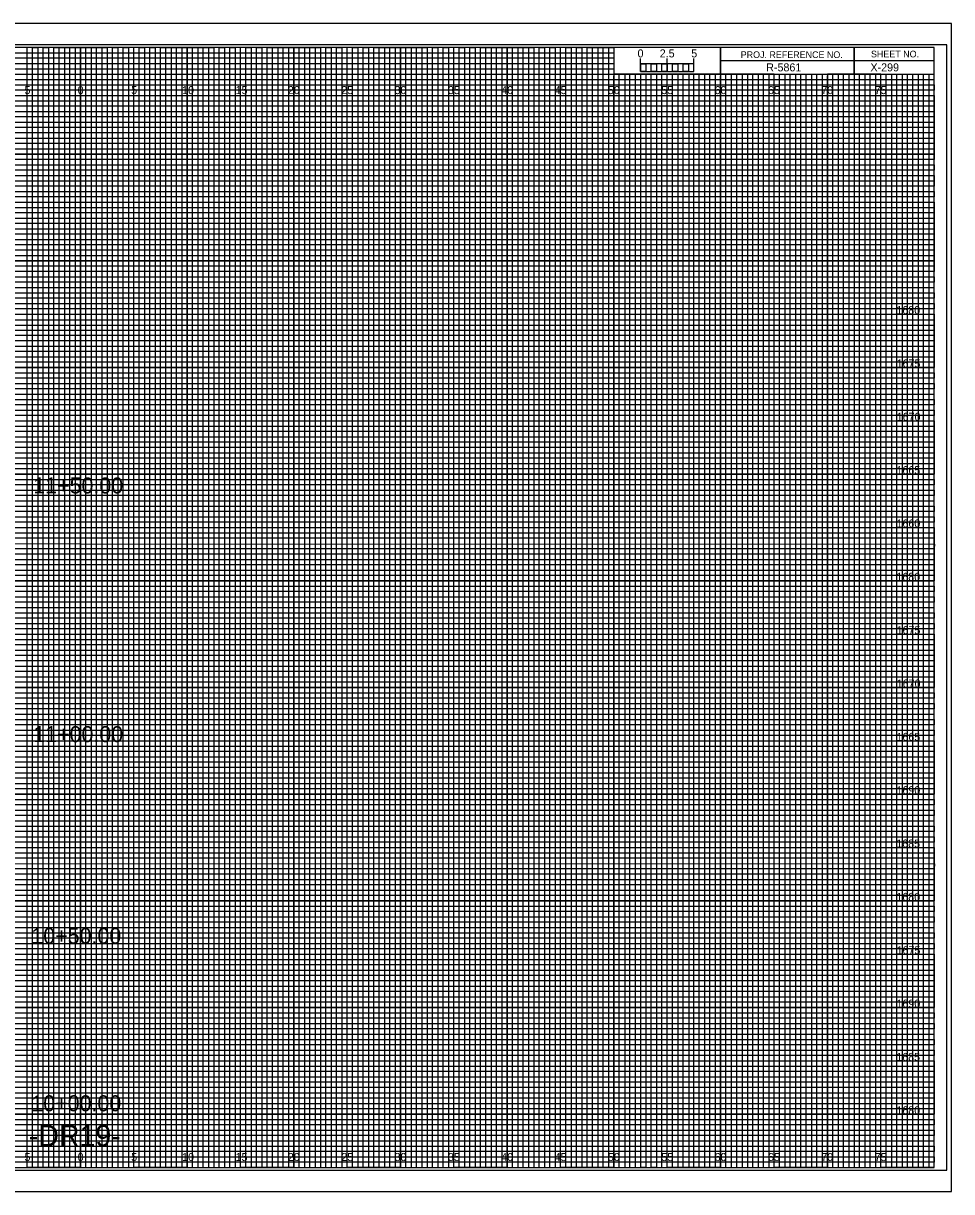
# Model space of a CAD drawing. Extents: x -7 to 162, y -2 to 107.
# Drawn here: x 74.6 to 161.7, y -2.3 to 107.3 of the extents above; entities that cross this region are included whole.
import ezdxf

# ---------------------------------------------------------------- set-up
doc = ezdxf.new("R2010")
doc.units = 0
for name, color, linetype in [('Prop XS Alignment Label', 7, 'Continuous'), ('Prop XS Bar Scale Labels', 7, 'Continuous'), ('Prop XS Elevation Labels', 7, 'Continuous'), ('Prop XS Offset Labels', 7, 'Continuous'), ('Prop XS Project Number', 7, 'Continuous'), ('Prop XS Sheet Number', 7, 'Continuous'), ('Prop XS Station Labels', 7, 'Continuous'), ('Sheet Cross Section CELL', 7, 'Continuous'), ('Sheet Cross Section Grid Major CELL', 7, 'Continuous'), ('Sheet Cross Section Grid Middle CELL', 7, 'Continuous'), ('Sheet Cross Section Grid Minor 1 CELL', 7, 'Continuous'), ('Sheet Cross Section Grid Minor 2 CELL', 7, 'Continuous'), ('Sheet Cross Section Scale CELL', 7, 'Continuous'), ('Sheet Cutting Line CELL', 7, 'Continuous'), ('Sheet DOT Grid CELL', 7, 'Continuous'), ('Sheet Plot Border Inside CELL', 7, 'Continuous'), ('Sheet Plot Border Outside CELL', 7, 'Continuous')]:
    doc.layers.add(name, color=color, linetype=linetype)

msp = doc.modelspace()

# ---------------------------------------------------------------- linework, layer by layer
at = {"layer": 'Sheet Cross Section CELL'}
for p, q in [((152.5, 105), (152.5, 102.5)), ((152.5, 102.5), (152.5, 105)), ((160, 103.75), (140, 103.75)), ((140, 103.75), (140, 102.5)), ((140, 102.5), (160, 102.5))]:
    msp.add_line(p, q, dxfattribs=at)
for points in [[(160, 105), (0, 105), (0, 0), (160, 0)], [(140, 105), (130, 105), (130, 102.52), (140, 102.52)], [(160, 105), (140, 105), (140, 102.5), (160, 102.5)]]:
    msp.add_lwpolyline(points, close=True, dxfattribs=at)
at = {"layer": 'Sheet Cross Section Grid Major CELL'}
for p, q in [((75, 105), (70, 105)), ((75, 0), (75, 105)), ((85, 105), (80, 105)), ((80, 105), (80, 0)), ((85, 0), (85, 105)), ((95, 105), (90, 105)), ((90, 105), (90, 0)), ((95, 0), (95, 105)), ((105, 105), (100, 105)), ((100, 105), (100, 0)), ((105, 0), (105, 105)), ((115, 105), (110, 105)), ((110, 105), (110, 0)), ((115, 0), (115, 105)), ((125, 105), (120, 105)), ((120, 105), (120, 0)), ((125, 0), (125, 105)), ((130, 105), (130, 0)), ((135, 0), (135, 102.5)), ((145, 102.5), (140, 102.5)), ((140, 102.5), (140, 0)), ((145, 0), (145, 102.5)), ((155, 102.5), (150, 102.5)), ((150, 102.5), (150, 0)), ((155, 0), (155, 102.5)), ((80, 0), (75, 0)), ((90, 0), (85, 0)), ((100, 0), (95, 0)), ((110, 0), (105, 0)), ((120, 0), (115, 0)), ((130, 0), (125, 0)), ((140, 0), (135, 0)), ((150, 0), (145, 0)), ((160, 0), (155, 0)), ((160, 0), (160, 0))]:
    msp.add_line(p, q, dxfattribs=at)
for points in [[(0, 100), (160, 100), (160, 95), (0, 95)], [(0, 90), (160, 90), (160, 85), (0, 85)], [(0, 80), (160, 80), (160, 75), (0, 75)], [(0, 70), (160, 70), (160, 65), (0, 65)], [(0, 60), (160, 60), (160, 55), (0, 55)], [(0, 50), (160, 50), (160, 45), (0, 45)], [(0, 40), (160, 40), (160, 35), (0, 35)], [(0, 30), (160, 30), (160, 25), (0, 25)], [(0, 20), (160, 20), (160, 15), (0, 15)], [(0, 10), (160, 10), (160, 5), (0, 5)]]:
    msp.add_lwpolyline(points, dxfattribs=at)
at = {"layer": 'Sheet Cross Section Grid Middle CELL'}
for points in [[(72.5, 0), (77.5, 0), (77.5, 105), (82.5, 105), (82.5, 0), (87.5, 0), (87.5, 105), (92.5, 105), (92.5, 0), (97.5, 0), (97.5, 105), (102.5, 105), (102.5, 0), (107.5, 0), (107.5, 105), (112.5, 105), (112.5, 0), (117.5, 0), (117.5, 105), (122.5, 105), (122.5, 0), (127.5, 0), (127.5, 105), (129.97, 105), (130, 105), (130, 102.5), (132.5, 102.5), (132.5, 0), (137.5, 0), (137.5, 102.5), (142.5, 102.5), (142.5, 0), (147.5, 0), (147.5, 102.5), (152.5, 102.5), (152.5, 0), (157.5, 0), (157.5, 102.5)], [(0, 102.5), (137.5, 102.5)], [(0, 92.5), (160, 92.5), (160, 97.5), (0, 97.5)], [(0, 82.5), (160, 82.5), (160, 87.5), (0, 87.5)], [(0, 72.5), (160, 72.5), (160, 77.5), (0, 77.5)], [(0, 62.5), (160, 62.5), (160, 67.5), (0, 67.5)], [(0, 52.5), (160, 52.5), (160, 57.5), (0, 57.5)], [(0, 42.5), (160, 42.5), (160, 47.5), (0, 47.5)], [(0, 32.5), (160, 32.5), (160, 37.5), (0, 37.5)], [(0, 22.5), (160, 22.5), (160, 27.5), (0, 27.5)], [(0, 12.5), (160, 12.5), (160, 17.5), (0, 17.5)], [(0, 2.5), (160, 2.5), (160, 7.5), (0, 7.5)]]:
    msp.add_lwpolyline(points, dxfattribs=at)
at = {"layer": 'Sheet Cross Section Grid Minor 1 CELL'}
for p, q in [((0, 104.5), (130, 104.5)), ((130, 104.5), (130, 103.99)), ((130, 103.99), (0, 103.99)), ((0, 103.5), (130, 103.5)), ((130, 102.95), (0, 102.95)), ((130, 103.5), (130, 102.95)), ((0, 102), (160, 102))]:
    msp.add_line(p, q, dxfattribs=at)
for points in [[(0, 101.5), (135, 101.5), (160, 101.5), (160, 101), (0, 101)], [(0, 100.5), (160, 100.5), (160, 99.5), (0, 99.5)], [(0, 99), (160, 99), (160, 98.5), (0, 98.49)], [(0, 98), (160, 98), (160, 97), (0, 97)], [(0, 96.5), (160, 96.5), (160, 96), (0, 96)], [(0, 95.5), (160, 95.5), (160, 94.5), (0, 94.5)], [(0, 94), (160, 94), (160, 93.5), (0, 93.5)], [(0, 93), (160, 93), (160, 92), (0, 92)], [(0, 91.5), (160, 91.5), (160, 91), (0, 91)], [(0, 90.5), (160, 90.5), (160, 89.5), (0, 89.5)], [(0, 89), (160, 89), (160, 88.5), (0, 88.5)], [(0, 88), (160, 88), (160, 86.98), (160, 86.5), (160, 86), (0, 86)], [(0, 87), (160, 87), (160, 86.5), (0, 86.5)], [(0, 85.5), (160, 85.5), (160, 84.5), (0, 84.52)], [(0, 84.52), (160, 84.5), (160, 84), (0, 84)], [(0, 83.5), (160, 83.5), (160, 83), (0, 83)], [(0, 82), (160, 82), (160, 81.5), (0, 81.5)], [(0, 81), (160, 81), (160, 80.5), (0, 80.5)], [(-0.04, 79.45), (160, 79.45), (160, 78.94), (-0.04, 78.94)], [(0, 78.5), (160, 78.5), (160, 78), (0, 78)], [(0, 77), (160, 77), (160, 76.5), (0, 76.5)], [(0, 76), (160, 76), (160, 75.5), (0, 75.5)], [(0, 74.5), (160, 74.5), (160, 74), (0, 74)], [(0, 73.5), (160, 73.5), (160, 73), (0, 73)], [(0, 72), (160, 72), (160, 71.5), (0, 71.5)], [(0, 71), (160, 71), (160, 70.5), (0, 70.5)], [(0, 69.5), (160, 69.5), (160, 68.99), (0, 69)], [(0, 68.5), (160, 68.5), (160, 68), (0, 68)], [(0, 67), (160, 67), (160, 66.5), (0, 66.5)], [(0, 66), (160, 66), (160, 65.5), (0, 65.5)], [(0, 64.5), (160, 64.5), (160, 64), (0, 64)], [(0, 63.5), (160, 63.5), (160, 63), (0, 63)], [(0, 62), (160, 62), (160, 61.5), (0, 61.5)], [(0, 61), (160, 61), (160, 60.5), (0, 60.5)], [(0, 59.5), (160, 59.5), (160, 59), (0, 59)], [(0, 58.5), (160.03, 58.45), (160, 58), (0, 58)], [(0, 57), (160, 57), (160, 56.5), (0, 56.5)], [(0, 56), (160, 56), (160, 55.5), (0, 55.5)], [(0, 54.5), (160, 54.5), (160, 54), (0, 54)], [(0, 53.5), (160, 53.5), (160, 53), (0, 53)], [(0, 52), (160, 52), (160, 51.5), (0, 51.5)], [(0, 51), (160, 51), (160, 50.5), (0, 50.5)], [(0, 49.5), (160, 49.5), (160, 49), (0, 49)], [(0, 48.5), (160, 48.5), (160, 48), (0, 48)], [(0, 47), (160, 47), (160, 46.5), (0, 46.5)], [(0, 46), (160, 46), (160, 45.5), (0, 45.5)], [(0, 44.5), (160, 44.5), (160, 44), (0, 44)], [(0, 43.5), (160, 43.5), (160, 43), (0, 43)], [(0, 42), (160, 42), (160, 41.5), (0, 41.5)], [(0, 41), (160, 41), (160, 40.5), (0, 40.5)], [(0, 39.5), (160, 39.5), (160, 38.99), (0, 39)], [(0, 38.5), (160, 38.5), (160, 38), (0, 38)], [(0, 37), (160, 37), (160, 36.5), (0, 36.5)], [(0, 36), (160, 36), (160, 35.5), (0, 35.5)], [(0, 34.5), (160, 34.5), (160, 34), (0, 34)], [(0, 33.5), (160, 33.5), (160, 33), (0, 33)], [(0, 32), (160, 32), (160, 31.5), (0, 31.5)], [(0, 31), (160, 31), (160, 30.5), (0, 30.5)], [(0, 29.5), (160, 29.5), (160, 29), (0, 29)], [(0, 28.5), (160.03, 28.46), (160, 28), (0, 28)], [(0, 27), (160, 27), (160, 26.5), (0, 26.5)], [(0, 26), (160, 26), (160, 25.5), (0, 25.5)], [(0, 24.5), (160, 24.5), (160, 24), (0, 24)], [(0, 23.5), (160, 23.5), (160, 23), (0, 23)], [(0, 22), (160, 22), (160, 21.5), (0, 21.5)], [(0, 21), (160, 21), (160, 20.5), (0, 20.5)], [(0, 19.5), (160, 19.5), (160, 19), (0, 19)], [(0, 18.5), (160, 18.5), (160, 18), (0, 18)], [(0, 17), (160, 17), (160, 16.5), (0, 16.5)], [(0, 16), (160, 16), (160, 15.5), (0, 15.5)], [(0, 14.5), (160, 14.5), (160, 14), (0, 14)], [(0, 13.5), (160, 13.5), (160, 13), (0, 13)], [(0, 12), (160, 12), (160, 11.5), (0, 11.5)], [(0, 11), (160, 11), (160, 10.5), (0, 10.5)], [(0, 9.5), (160, 9.5), (160, 9), (0, 9)], [(0, 8.5), (160, 8.5), (160, 8), (0, 8)], [(0, 7), (160, 7), (160, 6.5), (0, 6.5)], [(0, 6), (160, 6), (160, 5.5), (0, 5.5)], [(0, 4.5), (160, 4.5), (160, 4), (0, 4)], [(0, 3.5), (160, 3.5), (160, 3), (0, 3)], [(0, 2), (160, 2), (160, 1.5), (0, 1.5)], [(0, 1), (160, 1), (160, 0.5), (0, 0.5)]]:
    msp.add_lwpolyline(points, dxfattribs=at)
at = {"layer": 'Sheet Cross Section Grid Minor 2 CELL'}
for p, q in [((133.5, 102.5), (133, 102.5)), ((133, 102.5), (133, 0)), ((133.5, 0), (133.5, 102.5)), ((134.5, 102.5), (134, 102.5)), ((134, 102.5), (134, 0)), ((134.5, 0), (134.5, 102.5)), ((133, 0), (132.5, 0)), ((134, 0), (133.5, 0))]:
    msp.add_line(p, q, dxfattribs=at)
for points in [[(75, 0), (75.5, 0), (75.5, 105), (76, 105), (76, 0)], [(76, 0), (76.5, 0), (76.5, 105), (77, 105), (77, 0)], [(77.5, 0), (78, 0), (78, 105), (78.5, 105), (78.5, 0)], [(78.5, 0), (79, 0), (79, 105), (79.5, 105), (79.5, 0)], [(80, 0), (80.5, 0), (80.5, 105), (81, 105), (81, 0)], [(81, 0), (81.5, 0), (81.5, 105), (82, 105), (82, 0)], [(82.5, 0), (83, 0), (83, 105), (83.5, 105), (83.5, 0)], [(83.5, 0), (84, 0), (84, 105), (84.5, 105), (84.5, 0)], [(85, 0), (85.5, 0), (85.5, 105), (86, 105), (86, 0)], [(86, 0), (86.5, 0), (86.5, 105), (87, 105), (87, 0)], [(87.5, 0), (88, 0), (88, 105), (88.5, 105), (88.5, 0)], [(88.5, 0), (89, 0), (89, 105), (89.5, 105), (89.5, 0)], [(90, 0), (90.5, 0), (90.5, 105), (91, 105), (91, 0)], [(91, 0), (91.5, 0), (91.5, 105), (92, 105), (92, 0)], [(92.5, 0), (93, 0), (93, 105), (93.5, 105), (93.5, 0)], [(93.5, 0), (94, 0), (94, 105), (94.5, 105), (94.5, 0)], [(95, 0), (95.5, 0), (95.5, 105), (96, 105), (96, 0)], [(96, 0), (96.5, 0), (96.5, 105), (97, 105), (97, 0)], [(97.5, 0), (98, 0), (98, 105), (98.5, 105), (98.5, 0)], [(98.5, 0), (99, 0), (99, 105), (99.5, 105), (99.5, 0)], [(100, 0), (100.5, 0), (100.5, 105), (101, 105), (101, 0)], [(101, 0), (101.5, 0), (101.5, 105), (102, 105), (102, 0)], [(102.5, 0), (103, 0), (103, 105), (103.5, 105), (103.5, 0)], [(103.5, 0), (104, 0), (104, 105), (104.5, 105), (104.5, 0)], [(105, 0), (105.5, 0), (105.5, 105), (106, 105), (106, 0)], [(106, 0), (106.5, 0), (106.5, 105), (107, 105), (107, 0)], [(107.5, 0), (108, 0), (108, 105), (108.5, 105), (108.5, 0)], [(108.5, 0), (109, 0), (109, 105), (109.5, 105), (109.5, 0)], [(110, 0), (110.5, 0), (110.5, 105), (111, 105), (111, 0)], [(111, 0), (111.5, 0), (111.5, 105), (112, 105), (112, 0)], [(112.5, 0), (113, 0), (113, 105), (113.5, 105), (113.5, 0)], [(113.5, 0), (114, 0), (114, 105), (114.5, 105), (114.5, 0)], [(115, 0), (115.5, 0), (115.5, 105), (116, 105), (116, 0)], [(116, 0), (116.5, 0), (116.5, 105), (117, 105), (117, 0)], [(117.5, 0), (118, 0), (118, 105), (118.5, 105), (118.5, 0)], [(118.5, 0), (119, 0), (119, 105), (119.5, 105), (119.5, 0)], [(120, 0), (120.5, 0), (120.5, 105), (121, 105), (121, 0)], [(121, 0), (121.5, 0), (121.5, 105), (122, 105), (122, 0)], [(122.5, 0), (123, 0), (123, 105), (123.5, 105), (123.5, 0)], [(123.5, 0), (124, 0), (124, 105), (124.5, 105), (124.5, 0)], [(125, 0), (125.5, 0), (125.5, 105), (126, 105), (126, 0)], [(126, 0), (126.5, 0), (126.5, 105), (127, 105), (127, 0)], [(127.5, 0), (128, 0), (128, 105), (128.5, 105), (128.5, 0)], [(128.5, 0), (129, 0), (129, 105), (129.5, 105), (129.5, 0)], [(130, 0), (130.5, 0), (130.5, 102.5), (131.01, 102.5), (131.01, 0)], [(131, 0), (131.5, 0), (131.5, 102.5), (132, 102.5), (132, 0)], [(135, 0), (135.49, 0), (135.49, 102.5), (136, 102.5), (136, 0)], [(136, 0), (136.5, 0), (136.5, 102.5), (137.03, 102.5), (137.03, 0)], [(137.5, 0), (138, 0), (138, 102.5), (138.5, 102.5), (138.5, 0)], [(138.5, 0), (139, 0), (139, 102.5), (139.5, 102.5), (139.5, 0)], [(140, 0), (140.5, 0), (140.5, 102.5), (141, 102.5), (141, 0)], [(141, 0), (141.5, 0), (141.5, 102.5), (142, 102.5), (142, 0)], [(142.5, 0), (143, 0), (143, 102.5), (143.5, 102.5), (143.5, 0)], [(143.5, 0), (144, 0), (144, 102.5), (144.5, 102.5), (144.5, 0)], [(145, 0), (145.5, 0), (145.5, 102.5), (146, 102.5), (146, 0)], [(146, 0), (146.5, 0), (146.5, 102.5), (147, 102.5), (147, 0)], [(147.5, 0), (148, 0), (148, 102.5), (148.5, 102.5), (148.5, 0)], [(148.5, 0), (149, 0), (149, 102.5), (149.5, 102.5), (149.5, 0)], [(150, 0), (150.5, 0), (150.5, 102.5), (151, 102.5), (151, 0)], [(151, 0), (151.5, 0), (151.5, 102.5), (152, 102.5), (152, 0)], [(152.5, 0), (153, 0), (153, 102.5), (153.5, 102.5), (153.5, 0)], [(153.5, 0), (154, 0), (154, 102.5), (154.5, 102.5), (154.5, 0)], [(155, 0), (155.5, 0), (155.5, 102.5), (156, 102.5), (156, 0)], [(156, 0), (156.5, 0), (156.5, 102.5), (157, 102.5), (157, 0)], [(157.5, 0), (158, 0), (158, 102.5), (158.5, 102.5), (158.5, 0)], [(158.5, 0), (159, 0), (159, 102.5), (159.5, 102.5), (159.5, 0)]]:
    msp.add_lwpolyline(points, dxfattribs=at)
at = {"layer": 'Sheet Cross Section Scale CELL'}
for p, q in [((132.5, 102.75), (132.5, 103.95)), ((132.5, 103.45), (132.5, 103.95)), ((135, 102.75), (135, 103.95)), ((137.5, 102.75), (137.5, 103.95)), ((137.5, 103.45), (137.5, 103.95))]:
    msp.add_line(p, q, dxfattribs=at)
for points in [[(137.5, 103.45), (132.5, 103.45), (132.5, 102.75), (137.5, 102.75)], [(132.5, 103.45), (133, 103.45), (133, 102.75), (132.5, 102.75)], [(133.5, 103.45), (134, 103.45), (134, 102.75), (133.5, 102.75)], [(134.5, 103.45), (135, 103.45), (135, 102.75), (134.5, 102.75)], [(135.5, 103.45), (136, 103.45), (136, 102.75), (135.5, 102.75)], [(136.5, 103.45), (137, 103.45), (137, 102.75), (136.5, 102.75)]]:
    msp.add_lwpolyline(points, close=True, dxfattribs=at)
at = {"layer": 'Sheet Cutting Line CELL'}
for p, q in [((161.65, 107.25), (-6.7, 107.25)), ((-6.7, -2.25), (161.65, -2.25))]:
    msp.add_line(p, q, dxfattribs=at)
at = {"layer": 'Sheet DOT Grid CELL'}
for p, q in [((75, 0), (75, 105)), ((80, 0), (80, 105)), ((85, 0), (85, 105)), ((90, 0), (90, 105)), ((95, 0), (95, 105)), ((100, 0), (100, 105)), ((105, 0), (105, 105)), ((110, 0), (110, 105)), ((115, 0), (115, 105)), ((120, 0), (120, 105)), ((125, 0), (125, 105)), ((130, 0), (130, 102.34)), ((135, 0), (135, 102.34)), ((140, 0), (140, 102.34)), ((145, 0), (145, 102.34)), ((150, 0), (150, 102.34)), ((155, 0), (155, 102.34)), ((0, 100), (160, 100)), ((0, 95), (160, 95)), ((0, 90), (160, 90)), ((0, 85), (160, 85)), ((0, 80), (160, 80)), ((0, 75), (160, 75)), ((0, 70), (160, 70)), ((0, 65), (160, 65)), ((0, 60), (160, 60)), ((0, 55), (160, 55)), ((0, 50), (160, 50)), ((0, 45), (160, 45)), ((0, 40), (160, 40)), ((0, 35), (160, 35)), ((0, 30), (160, 30)), ((0, 25), (160, 25)), ((0, 20), (160, 20)), ((0, 15), (160, 15)), ((0, 10), (160, 10)), ((0, 5), (160, 5))]:
    msp.add_line(p, q, dxfattribs=at)
at = {"layer": 'Sheet Plot Border Inside CELL'}
msp.add_lwpolyline([(-5.4, -0.25), (161.2, -0.25), (161.2, 105.25), (-5.4, 105.25)], close=True, dxfattribs=at)
at = {"layer": 'Sheet Plot Border Outside CELL'}
msp.add_lwpolyline([(-6.7, -2.25), (161.65, -2.25), (161.65, 107.25), (-6.7, 107.25)], close=True, dxfattribs=at)

# ---------------------------------------------------------------- texts
at = {"layer": 'Prop XS Alignment Label'}
msp.add_text('-DR19-', height=2, dxfattribs=at).set_placement((75.15, 2))
at = {"layer": 'Prop XS Bar Scale Labels'}
for s, p in [('2.5', (134.29, 104.06)), ('5', (137.24, 104.06))]:
    msp.add_text(s, height=0.75, dxfattribs=at).set_placement(p)
at = {"layer": 'Prop XS Elevation Labels'}
for s, p in [('1680', (156.47, 80)), ('1675', (156.49, 75)), ('1670', (156.5, 70)), ('1665', (156.48, 65)), ('1660', (156.48, 60)), ('1680', (156.47, 55)), ('1675', (156.49, 50)), ('1670', (156.5, 45)), ('1665', (156.48, 40)), ('1690', (156.48, 35)), ('1685', (156.46, 30)), ('1680', (156.47, 25)), ('1675', (156.49, 20)), ('1690', (156.48, 15)), ('1685', (156.46, 10)), ('1680', (156.47, 5))]:
    msp.add_text(s, height=0.75, dxfattribs=at).set_placement(p)
at = {"layer": 'Prop XS Offset Labels'}
for s, p in [('5', (74.74, 100.62)), ('0', (79.73, 100.62)), ('0', (79.73, 100.62)), ('5', (84.74, 100.62)), ('10', (89.52, 100.62)), ('15', (94.53, 100.62)), ('20', (99.43, 100.62)), ('25', (104.44, 100.62)), ('30', (109.43, 100.62)), ('35', (114.44, 100.62)), ('40', (119.43, 100.62)), ('45', (124.44, 100.62)), ('50', (129.43, 100.62)), ('55', (134.44, 100.62)), ('60', (139.43, 100.62)), ('65', (144.44, 100.62)), ('70', (149.43, 100.62)), ('75', (154.44, 100.62)), ('5', (74.74, 0.62)), ('0', (79.73, 0.62)), ('0', (79.73, 0.62)), ('5', (84.74, 0.62)), ('10', (89.52, 0.62)), ('15', (94.53, 0.62)), ('20', (99.43, 0.62)), ('25', (104.44, 0.62)), ('30', (109.43, 0.62)), ('35', (114.44, 0.62)), ('40', (119.43, 0.62)), ('45', (124.44, 0.62)), ('50', (129.43, 0.62)), ('55', (134.44, 0.62)), ('60', (139.43, 0.62)), ('65', (144.44, 0.62)), ('70', (149.43, 0.62)), ('75', (154.44, 0.62))]:
    msp.add_text(s, height=0.75, dxfattribs=at).set_placement(p)
at = {"layer": 'Prop XS Project Number'}
msp.add_text('R-5861', height=0.75, dxfattribs=at).set_placement((144.27, 102.75))
at = {"layer": 'Prop XS Sheet Number'}
msp.add_text('X-299', height=0.75, dxfattribs=at).set_placement((154.04, 102.75))
at = {"layer": 'Prop XS Station Labels'}
for s, p in [('11+50.00', (75.57, 63.19)), ('11+00.00', (75.57, 39.88)), ('10+50.00', (75.39, 20.98)), ('10+00.00', (75.39, 5.28))]:
    msp.add_text(s, height=1.5, dxfattribs=at).set_placement(p)
at = {"layer": 'Sheet Cross Section CELL'}
for s, p in [('PROJ. REFERENCE NO.', (141.88, 104)), ('SHEET NO.', (154.09, 104.06))]:
    msp.add_text(s, height=0.625, dxfattribs=at).set_placement(p)
at = {"layer": 'Sheet Cross Section Scale CELL'}
msp.add_text('0', height=0.75, dxfattribs=at).set_placement((132.21, 104.06))

doc.saveas('drawing.dxf')
